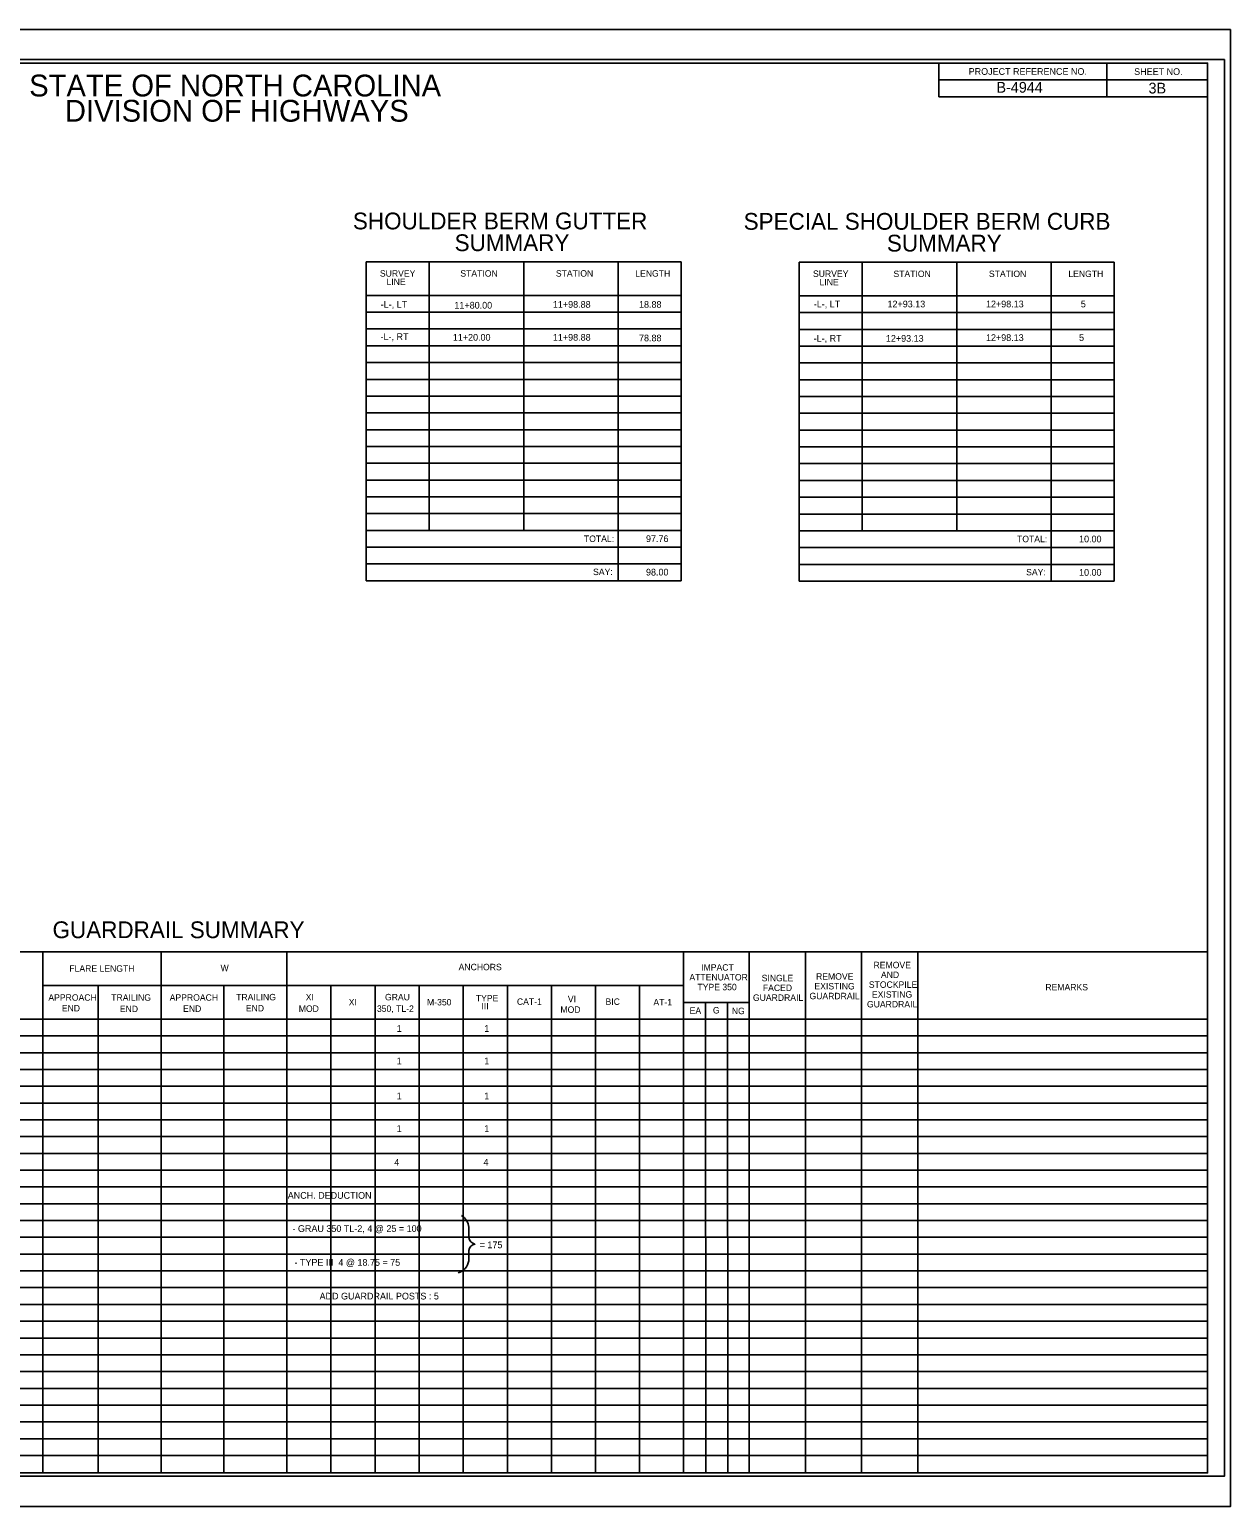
# Model space of a CAD drawing. Extents: x 575843 to 577531, y -53322 to -50954.
# Drawn here: x 576633 to 577527, y -53322 to -52222 of the extents above; entities that cross this region are included whole.
import ezdxf

# ---------------------------------------------------------------- set-up
doc = ezdxf.new("R2010")
doc.units = 0
for name, color, linetype in [('Default', 7, 'Continuous'), ('Sheet Cutting Line CELL', 7, 'Continuous'), ('Sheet Plot Border Inside CELL', 7, 'Continuous'), ('Sheet Plot Border Outside CELL', 7, 'Continuous'), ('Sheet Summary Combination CELL', 7, 'Continuous'), ('Sheet Summary Combination Grid CELL', 7, 'Continuous')]:
    doc.layers.add(name, color=color, linetype=linetype)

msp = doc.modelspace()

# ---------------------------------------------------------------- linework, layer by layer
at = {"layer": 'Default'}
for p, q in [((576959.9, -53113.6), (576959.9, -53121.4)), ((576959.9, -53130.9), (576959.9, -53138.6))]:
    msp.add_line(p, q, dxfattribs=at)
for centre, radius, start, end in [((576948.4, -53114.9), 11.7, 6.4995, 57.9457), ((576965.7, -53120.4), 5.83, 189.335, 258.9765), ((576965.7, -53131.9), 5.83, 100.4375, 169.9025), ((576948.5, -53136.4), 11.7, 287.3589, 348.7189)]:
    msp.add_arc(centre, radius, start, end, dxfattribs=at)
at = {"layer": 'Sheet Cutting Line CELL'}
for p, q in [((577527, -52221.6), (575843, -52221.6)), ((575843, -53321.6), (577527, -53321.6))]:
    msp.add_line(p, q, dxfattribs=at)
at = {"layer": 'Sheet Plot Border Inside CELL'}
msp.add_lwpolyline([(577522.5, -52244), (575856, -52244), (575856, -53299.1), (577522.5, -53299.1)], close=True, dxfattribs=at)
at = {"layer": 'Sheet Plot Border Outside CELL'}
msp.add_lwpolyline([(577527, -52221.6), (575843, -52221.6), (575843, -53321.6), (577527, -53321.6)], close=True, dxfattribs=at)
at = {"layer": 'Sheet Summary Combination CELL'}
for p, q in [((577435, -52246.6), (577435, -52271.6)), ((577309.9, -52259.1), (577510, -52259.1)), ((577309.9, -52271.6), (577510, -52271.6)), ((577024.9, -52394.7), (577024.9, -52394.7)), ((577031.1, -52394.8), (577031.1, -52394.8)), ((577040.2, -52394.6), (577040.2, -52394.6)), ((577045.8, -52394.7), (577045.8, -52394.7)), ((577347.3, -52394.9), (577347.3, -52394.9)), ((577353.5, -52395), (577353.5, -52395)), ((577362.6, -52394.8), (577362.6, -52394.8)), ((577368.2, -52394.9), (577368.2, -52394.9))]:
    msp.add_line(p, q, dxfattribs=at)
for points in [[(577510, -52246.6), (576010, -52246.6), (576010, -53296.6), (577510, -53296.6)], [(577309.9, -52246.6), (577510, -52246.6), (577510, -52271.6), (577309.9, -52271.6)]]:
    msp.add_lwpolyline(points, close=True, dxfattribs=at)
at = {"layer": 'Sheet Summary Combination Grid CELL'}
for p, q in [((576883.6, -52394.6), (577118.1, -52394.6)), ((576883.6, -52394.6), (576883.6, -52632.1)), ((576930.5, -52394.6), (576930.5, -52594.6)), ((577000.9, -52394.6), (577000.9, -52594.6)), ((577071.2, -52394.6), (577071.2, -52632.1)), ((577118.1, -52394.6), (577118.1, -52632.1)), ((577206, -52394.9), (577440.5, -52394.9)), ((577206, -52394.9), (577206, -52632.4)), ((577252.9, -52394.9), (577252.9, -52594.9)), ((577323.3, -52394.9), (577323.3, -52594.9)), ((577393.6, -52394.9), (577393.6, -52632.4)), ((577440.5, -52394.9), (577440.5, -52632.4)), ((576883.6, -52419.6), (577118.1, -52419.6)), ((577206, -52419.9), (577440.5, -52419.9)), ((576883.6, -52432.1), (577118.1, -52432.1)), ((577206, -52432.4), (577440.5, -52432.4)), ((576883.6, -52444.6), (577118.1, -52444.6)), ((577206, -52444.9), (577440.5, -52444.9)), ((576883.6, -52457.1), (577118.1, -52457.1)), ((577206, -52457.4), (577440.5, -52457.4)), ((576883.6, -52469.6), (577118.1, -52469.6)), ((577206, -52469.9), (577440.5, -52469.9)), ((576883.6, -52482.1), (577118.1, -52482.1)), ((577206, -52482.4), (577440.5, -52482.4)), ((576883.6, -52494.6), (577118.1, -52494.6)), ((577206, -52494.9), (577440.5, -52494.9)), ((576883.6, -52507.1), (577118.1, -52507.1)), ((577206, -52507.4), (577440.5, -52507.4)), ((576883.6, -52519.6), (577118.1, -52519.6)), ((577206, -52519.9), (577440.5, -52519.9)), ((576883.6, -52532.1), (577118.1, -52532.1)), ((577206, -52532.4), (577440.5, -52532.4)), ((576883.6, -52544.6), (577118.1, -52544.6)), ((577206, -52544.9), (577440.5, -52544.9)), ((576883.6, -52557.1), (577118.1, -52557.1)), ((577206, -52557.4), (577440.5, -52557.4)), ((576883.6, -52569.6), (577118.1, -52569.6)), ((576883.6, -52569.6), (577118.1, -52569.6)), ((577206, -52569.9), (577440.5, -52569.9)), ((577206, -52569.9), (577440.5, -52569.9)), ((576883.6, -52582.1), (577118.1, -52582.1)), ((577206, -52582.4), (577440.5, -52582.4)), ((576883.6, -52594.6), (577118.1, -52594.6)), ((577206, -52594.9), (577440.5, -52594.9)), ((576883.6, -52607.1), (577118.1, -52607.1)), ((577206, -52607.4), (577440.5, -52607.4)), ((576883.6, -52619.6), (577118.1, -52619.6)), ((577206, -52619.9), (577440.5, -52619.9)), ((576883.6, -52632.1), (577118.1, -52632.1)), ((577206, -52632.4), (577440.5, -52632.4)), ((576010, -52908.6), (577510, -52908.6)), ((576642.8, -52908.6), (576642.8, -53296.6)), ((576730.9, -52908.6), (576730.9, -53296.6)), ((576824.6, -52908.6), (576824.6, -53296.6)), ((577119.9, -52908.6), (577119.9, -53296.6)), ((577168.8, -52908.6), (577168.8, -53296.6)), ((577210.6, -52908.6), (577210.6, -53296.6)), ((577252.4, -52908.6), (577252.4, -53296.6)), ((577294.2, -52908.6), (577294.2, -53296.6)), ((577119.9, -52933.6), (576642.8, -52933.6)), ((576684, -52933.6), (576684, -53296.6)), ((576777.7, -52933.6), (576777.7, -53296.6)), ((576857.4, -52933.6), (576857.4, -53296.6)), ((576890.2, -52933.6), (576890.2, -53296.6)), ((576923.1, -52933.6), (576923.1, -53296.6)), ((576955.9, -52933.6), (576955.9, -53296.6)), ((576988.7, -52933.6), (576988.7, -53296.6)), ((577021.5, -52933.6), (577021.5, -53296.6)), ((577054.3, -52933.6), (577054.3, -53296.6)), ((577087.1, -52933.6), (577087.1, -53296.6)), ((577119.9, -52946.3), (577168.5, -52946.3)), ((577136.2, -52946.3), (577136.4, -53296.6)), ((577152.5, -52946.3), (577152.7, -53296.6)), ((576010, -52958.6), (577510, -52958.6)), ((576010, -52971.1), (577510, -52971.1)), ((576010, -52983.6), (577510, -52983.6)), ((576010, -52996.1), (577510, -52996.1)), ((576010, -53008.6), (577510, -53008.6)), ((576010, -53021.1), (577510, -53021.1)), ((576010, -53033.6), (577510, -53033.6)), ((576010, -53046.1), (577510, -53046.1)), ((576010, -53058.6), (577510, -53058.6)), ((576010, -53071.1), (577510, -53071.1)), ((576010, -53083.6), (577510, -53083.6)), ((576010, -53096.1), (577510, -53096.1)), ((576010, -53108.6), (577510, -53108.6)), ((576010, -53121.1), (577510, -53121.1)), ((576010, -53133.6), (577510, -53133.6)), ((576010, -53146.1), (577510, -53146.1)), ((576010, -53158.6), (577510, -53158.6)), ((576010, -53171.1), (577510, -53171.1)), ((576010, -53183.6), (577510, -53183.6)), ((576010, -53196.1), (577510, -53196.1)), ((576010, -53208.6), (577510, -53208.6)), ((576010, -53221.1), (577510, -53221.1)), ((576010, -53233.6), (577510, -53233.6)), ((576010, -53246.1), (577510, -53246.1)), ((576010, -53258.6), (577510, -53258.6)), ((576010, -53271.1), (577510, -53271.1)), ((576010, -53283.6), (577510, -53283.6))]:
    msp.add_line(p, q, dxfattribs=at)

# ---------------------------------------------------------------- texts
at = {"layer": 'Default'}
for s, height, p in [('B-4944', 8, (577352.8, -52268.6)), ('3B', 8, (577466, -52269.2)), ('-L-, LT', 5, (576894.4, -52428.8)), ('11+80.00', 5, (576949.3, -52429.4)), ('11+98.88', 5, (577022.6, -52428.8)), ('18.88', 5, (577086.7, -52428.8)), ('-L-, LT', 5, (577216.8, -52428.5)), ('12+93.13', 5, (577271.7, -52428.5)), ('12+98.13', 5, (577345, -52428.5)), ('5', 5, (577415.6, -52428.5)), ('-L-, RT', 5, (576894.3, -52452.8)), ('11+20.00', 5, (576948.1, -52453.3)), ('11+98.88', 5, (577022.6, -52453.3)), ('78.88', 5, (577086.7, -52453.8)), ('-L-, RT', 5, (577216.7, -52454.1)), ('12+93.13', 5, (577270.5, -52454.1)), ('12+98.13', 5, (577345, -52453.5)), ('5', 5, (577414.3, -52453.5)), ('97.76', 5, (577091.9, -52603.3)), ('10.00', 5, (577414.3, -52603.5)), ('98.00', 5, (577091.9, -52628.2)), ('10.00', 5, (577414.3, -52628.4)), ('1', 5, (576906.3, -52968.1)), ('1', 5, (576971.5, -52968.1)), ('1', 5, (576906.3, -52992.2)), ('1', 5, (576971.5, -52992.2)), ('1', 5, (576906.3, -53018.3)), ('1', 5, (576971.5, -53018.3)), ('1', 5, (576906.3, -53042.6)), ('1', 5, (576971.5, -53042.6)), ('4', 5, (576904.5, -53067.7)), ('4', 5, (576970.9, -53067.7)), ('ANCH. DEDUCTION :', 5, (576825.2, -53092.4)), ('- GRAU 350 TL-2, 4 @ 25 = 100', 5, (576828.7, -53117.1)), ('= 175', 5, (576968.1, -53129.2)), ('- TYPE III  4 @ 18.75 = 75', 5, (576830.2, -53142.3)), ('ADD GUARDRAIL POSTS : 5', 5, (576848.9, -53167.4))]:
    msp.add_text(s, height=height, dxfattribs=at).set_placement(p)
at = {"layer": 'Sheet Summary Combination CELL'}
for s, height, p in [('STATE OF NORTH CAROLINA', 16.25, (576632.7, -52271.4)), ('PROJECT REFERENCE NO.', 5, (577332.1, -52255.3)), ('SHEET NO.', 5, (577455.3, -52255.4)), ('DIVISION OF HIGHWAYS', 16.25, (576659.3, -52290.2)), ('SURVEY', 4.8, (576893.8, -52405.6)), ('STATION', 4.8, (576953.7, -52405.6)), ('STATION', 4.8, (577024.8, -52405.6)), ('LENGTH', 4.8, (577083.9, -52405.6)), ('SURVEY', 4.8, (577216.2, -52405.8)), ('STATION', 4.8, (577276.1, -52405.9)), ('STATION', 4.8, (577347.2, -52405.9)), ('LENGTH', 4.8, (577406.3, -52405.9)), ('LINE', 4.8, (576898.7, -52411.9)), ('LINE', 4.8, (577221.1, -52412.1)), ('TOTAL:', 4.8, (577045.7, -52603.2)), ('TOTAL:', 4.8, (577368.1, -52603.4)), ('SAY:', 4.8, (577052.5, -52627.9)), ('SAY:', 4.8, (577374.9, -52628.1)), ('GUARDRAIL SUMMARY', 12.5, (576650.1, -52898.3)), ('FLARE LENGTH', 4.8, (576662.6, -52923.3)), ('W', 4.8, (576775.2, -52922.9)), ('ANCHORS', 4.8, (576952.4, -52922.2)), ('IMPACT', 4.8, (577133, -52922.5)), ('REMOVE', 4.8, (577261.3, -52920.7)), ('ATTENUATOR', 4.8, (577124.2, -52929.8)), ('SINGLE', 4.8, (577178, -52930.4)), ('EXISTING', 4.8, (577217.3, -52936.5)), ('REMOVE', 4.8, (577218.5, -52929.2)), ('STOCKPILE', 4.8, (577257.8, -52935.3)), ('AND', 4.8, (577266.8, -52928)), ('APPROACH', 4.8, (576647, -52944.9)), ('TRAILING', 4.8, (576693.8, -52944.9)), ('APPROACH', 4.8, (576737.3, -52944.9)), ('TRAILING', 4.8, (576786.8, -52944.6)), ('XI', 4.8, (576838.6, -52944.7)), ('GRAU', 4.8, (576897.6, -52944.6)), ('TYPE', 4.8, (576965.2, -52945.4)), ('VI', 4.8, (577033.7, -52946)), ('TYPE 350', 4.8, (577130.2, -52937.1)), ('GUARDRAIL', 4.8, (577171.5, -52945)), ('FACED', 4.8, (577178.9, -52937.7)), ('GUARDRAIL', 4.8, (577213.6, -52943.8)), ('EXISTING', 4.8, (577260.1, -52942.6)), ('REMARKS', 4.8, (577389.2, -52937.2)), ('END', 4.8, (576657, -52952.9)), ('END', 4.8, (576700.2, -52953.4)), ('END', 4.8, (576747.3, -52953.2)), ('END', 4.8, (576794, -52952.9)), ('MOD', 4.8, (576833.4, -52953.2)), ('XI', 4.8, (576870.6, -52948.4)), ('350, TL-2', 4.8, (576891.6, -52953.2)), ('M-350', 4.8, (576928.9, -52948.4)), ('III', 4.8, (576969.4, -52951.4)), ('CAT-1', 4.8, (576995.8, -52948)), ('MOD', 4.8, (577028.2, -52953.9)), ('BIC', 4.8, (577061.8, -52948)), ('AT-1', 4.8, (577097.4, -52948.4)), ('EA', 4.8, (577124.4, -52954.7)), ('G', 4.8, (577141.7, -52954.4)), ('NG', 4.8, (577155.8, -52954.9)), ('GUARDRAIL', 4.8, (577256.4, -52949.9))]:
    msp.add_text(s, height=height, dxfattribs=at).set_placement(p)
for s, p in [('SHOULDER BERM GUTTER', (576873.7, -52370.4)), ('SPECIAL SHOULDER BERM CURB', (577164.6, -52370.7)), (' SUMMARY', (576944.8, -52386.6)), (' SUMMARY', (577266.6, -52386.9))]:
    msp.add_text(s, height=12.5, rotation=0.0119, dxfattribs=at).set_placement(p)

doc.saveas('drawing.dxf')
